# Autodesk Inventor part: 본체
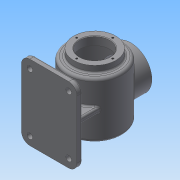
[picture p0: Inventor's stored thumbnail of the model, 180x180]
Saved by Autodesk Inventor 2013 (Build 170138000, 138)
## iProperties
Created: 2016-09
Part Number: 본체
Material: Generic
Document SubType Name: Modeling
Designer: Administrator
Density: 1 g/cm^3
Author: Administrator
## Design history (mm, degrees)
sketch "스케치1"
  geometry: C1 r 38 at (0, 0); 1 further point
  constraints: 1 centre point, 1 coincident
  dimensions: "d0" = 76 diameter of C1
extrude "돌출1" new body sketch "스케치1" distance "d1" = 12; taper "d2" = 0 deg
sketch "스케치2"
  geometry: C1 r 38 at (0, 0) reference; C2 r 50 at (0, 0)
  constraints: 1 centre point, 1 coincident
  dimensions: "d3" = 100 diameter of C2
extrude "돌출2" join sketch "스케치2" distance "d4" = 110; taper "d5" = 0 deg
node "작업 평면1"
node "작업 평면2"
sketch "스케치4"
  geometry: L1 (50, -12)-(-50, -12) reference; L2 (-50, -122)-(50, -122) reference; L3 (-38, -12)-(38, -12) reference; L4 (-38, 0)-(38, 0) reference; L5 (50, -61)-(50, 6.5); L6 (50, 6.5)-(-50, 6.5); L7 (-50, 6.5)-(-50, -128.5); L8 (-50, -128.5)-(50, -128.5); L9 (50, -128.5)-(50, -61)
  constraints: 10 end point, 2 perpendicular, 1 parallel
extrude "돌출4" join sketch "스케치4" distance "d17" = 10; taper "d18" = 0 deg
sketch "스케치5"
  geometry: L1 (-72, -21)-(21.167, -29.151); 1 further point
  constraints: 2 end point
node "작업 평면3"
sketch "스케치6"
  geometry: L1 (0, 0)-(40, 0); L2 (40, 0)-(40, -82); L3 (40, -82)-(-40, -82); L4 (-40, -82)-(-40, 0); L5 (-40, 0)-(0, 0)
  constraints: 10 end point, 3 perpendicular, 1 horizontal, 1 parallel
extrude "돌출5" join sketch "스케치6" stored distance "d28" = 10; taper "d29" = 0 deg
feature "리브1" dims "d30" = 1, "d31" = 10, "d32" = 0, "d33" = 0, "d34" = 1, "d35" = 1
sketch "스케치7"
  geometry: L1 (0, 0)-(0, -122); L2 (0, -122)-(50, -122); L3 (0, -122)-(-50, -122); L4 (0, -122)-(0, -122); L5 (-50, -110.562)-(-50, -122); L6 (-50, -122)-(0, -122); A1 r 115 centre (0, -7) between (-50, -110.562) and (0, -122)
  constraints: 12 end point, 2 perpendicular, 2 point on circle, 1 centre point, 1 collinear, 1 tangent, 1 vertical
revolve "회전1" sketch "스케치7" stored, may be unused: angle "d40" = 90 deg
sketch "스케치8"
  geometry: L1 (50, -110.562)-(50, -12); L2 (50, -12)-(-50, -12) reference; L3 (47, -15)-(47, -108.661); L4 (47, -15)-(0, -15); L5 (0, -12)-(0, -122); A1 r 115 centre (0, -7) between (-50, -110.562) and (50, -110.562) reference; A2 r 112 centre (0, -7) between (0, -119) and (47, -108.661); 1 further point
  constraints: 8 end point, 3 point on circle, 3 point on line, 1 centre point, 1 midpoint, 1 parallel
revolve "회전2" sketch "스케치8" stored, may be unused: angle "d45" = 90 deg
sketch "스케치9"
  geometry: C1 r 38 at (0, 0) reference; C2 r 27 at (0, 0)
  constraints: 1 centre point, 1 coincident
  dimensions: "d46" = 54 diameter of C2
extrude "돌출6" cut sketch "스케치9" distance "d47" = 15; taper "d48" = 0 deg
fillet "모깎기1" dims "d52" = 15, "d53" = 5, "d54" = 2, "d55" = 3
fillet "모깎기2" dims "d56" = 3
chamfer "모따기1" distance "d57" = 1; stored, may be unused: second distance "d58" = 2, angle "d59" = 45 deg
sketch "스케치11"
  geometry: 1 further point
hole "구멍1" sketch "스케치11" at (0, 32.5) diameter "d61" = 3.459; stored, may be unused: countersink angle "d65" = 90 deg, drill point angle "d67" = 118 deg; dims "d62" = 8, "d63" = 4, "d64" = 2, "d66" = 10
sketch "스케치13"
  geometry: C1 r 5 at (-35, -8.5); A1 r 15 centre (-35, -8.5) between (-35, 6.5) and (-50, -8.5) reference; 1 further point
  constraints: 1 centre point, 1 coincident
  dimensions: "d82" = 10 diameter of C1
extrude "돌출8" cut sketch "스케치13" stored distance "d83" = 15; taper "d84" = 0 deg
node "작업 평면4"
node "작업 평면5"
sketch "스케치14"
  geometry: 2 further points
  constraints: 1 other
feature "엠보싱1" sketch "스케치14" dims "d0" = 76, "d87" = 1, "d88" = 0
node "작업 평면6"
sketch "스케치15"
  geometry: L1 (0, 0)-(0, -12); L2 (0, -12)-(0, -62); C1 r 38 at (0, -62)
  constraints: 4 end point, 1 centre point, 1 coincident, 1 collinear, 1 vertical
  dimensions: "d90" = 12 distance of L1.start L1.end; "d91" = 50 distance of L1.end L2.end; "d92" = 76 diameter of C1
extrude "돌출9" join sketch "스케치15" stored distance "d93" = 15; taper "d94" = 0 deg
sketch "스케치16"
  geometry: C1 r 38 at (0, 0) reference; C2 r 27 at (0, 0); 1 further point
  constraints: 1 centre point, 1 coincident
  dimensions: "d95" = 54 diameter of C2
extrude "돌출10" cut sketch "스케치16" stored distance "d96" = 15; taper "d97" = 0 deg
sketch "스케치17"
  geometry: 2 further points
hole "구멍3" sketch "스케치17" at (0, 32.5) diameter "d99" = 3.459; stored, may be unused: countersink angle "d103" = 90 deg, drill point angle "d105" = 118 deg; dims "d100" = 8, "d101" = 4, "d102" = 2, "d104" = 10
chamfer "모따기2" distance "d109" = 1; stored, may be unused: second distance "d110" = 2, angle "d111" = 45 deg
fillet "모깎기3" dims "d112" = 3
node "솔리드1"
mirror "대칭1"
pattern_circular "원형 패턴1" dims angle "d69" = 360 deg
mirror "대칭2"
mirror "대칭3"
pattern_circular "원형 패턴3" dims angle "d107" = 360 deg
node "투영된 루프1"
node "투영된 루프2"
other parameters: "d6" = 65, "d11" = -82, "d24" = -61, "d85" = 0, "d86" = -122.5, "d89" = -147
